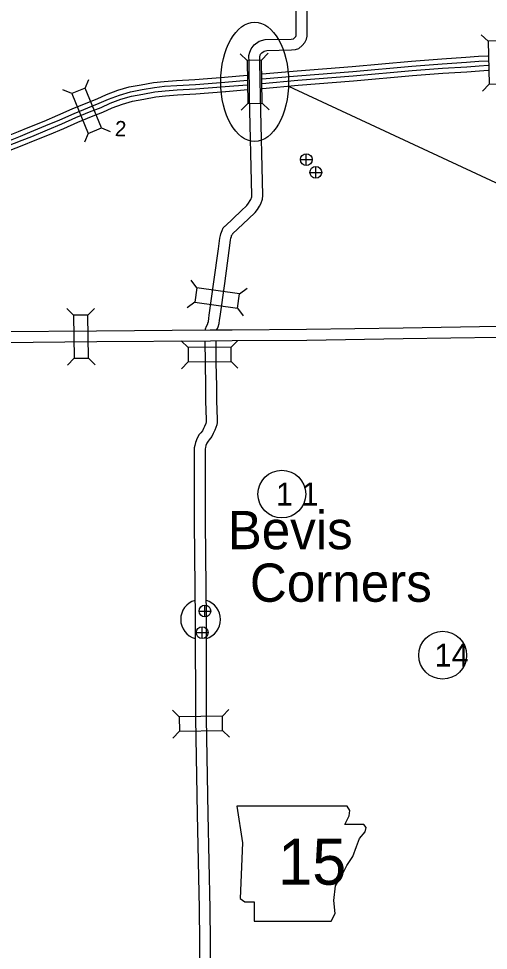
# Model space of a CAD drawing. Extents: x 1127717 to 1741049, y 2026793 to 2244711.
# Drawn here: x 1250609 to 1257093, y 2127719 to 2140586 of the extents above; entities that cross this region are included whole.
import ezdxf

# ---------------------------------------------------------------- set-up
doc = ezdxf.new("R2010")
doc.units = 0
for name, color, linetype in [('10', 7, 'Continuous'), ('15', 7, 'Continuous'), ('19', 7, 'Continuous'), ('20', 7, 'Continuous'), ('21', 7, 'Continuous'), ('24', 7, 'Continuous'), ('26', 7, 'Continuous'), ('27', 7, 'Continuous'), ('R_Draft', 7, 'Continuous')]:
    doc.layers.add(name, color=color, linetype=linetype)

msp = doc.modelspace()

# ---------------------------------------------------------------- linework, layer by layer
at = {"layer": '10'}
for points in [[(1253458, 2137722), (1253680, 2137932), (1253760, 2138007), (1253783, 2138037), (1253807, 2138073), (1253816, 2138090), (1253827, 2138123), (1253829, 2138145), (1253797, 2139504), (1253789, 2139984), (1253788, 2140075), (1253798, 2140122), (1253817, 2140171), (1253861, 2140222), (1253929, 2140273), (1254012, 2140297), (1254369, 2140303), (1254397, 2140305), (1254402, 2140307), (1254418, 2140320), (1254434, 2140340), (1254440, 2140351), (1254442, 2140361), (1254442, 2140382), (1254436, 2141102)], [(1253561, 2137613), (1253783, 2137823), (1253872, 2137907), (1253906, 2137951), (1253934, 2137994), (1253954, 2138028), (1253976, 2138095), (1253979, 2138142), (1253947, 2139506), (1253939, 2139986), (1253938, 2140060), (1253942, 2140080), (1253947, 2140093), (1253964, 2140112), (1253997, 2140137), (1254034, 2140148), (1254377, 2140153), (1254430, 2140158), (1254477, 2140175), (1254524, 2140213), (1254561, 2140258), (1254583, 2140301), (1254591, 2140344), (1254592, 2140381), (1254586, 2141104)], [(1253186, 2136293), (1253186, 2136300), (1253200, 2136338), (1253219, 2136373), (1253222, 2136381), (1253228, 2136403), (1253234, 2136443), (1253240, 2136493), (1253305, 2136951), (1253366, 2137405), (1253385, 2137552), (1253394, 2137593), (1253402, 2137616), (1253407, 2137636), (1253417, 2137661), (1253432, 2137695), (1253455, 2137719)], [(1253346, 2136292), (1253353, 2136306), (1253365, 2136331), (1253375, 2136374), (1253383, 2136422), (1253389, 2136474), (1253454, 2136930), (1253515, 2137386), (1253533, 2137526), (1253539, 2137553), (1253546, 2137576), (1253549, 2137589), (1253555, 2137600), (1253559, 2137610), (1253564, 2137616)], [(1253180, 2136131), (1253182, 2135831), (1253189, 2135508), (1253190, 2135304), (1253199, 2135052), (1253198, 2135020), (1253195, 2134997)], [(1253330, 2136133), (1253332, 2135833), (1253339, 2135510), (1253340, 2135307), (1253349, 2135053), (1253348, 2135009), (1253344, 2134977)], [(1253195, 2134997), (1253175, 2134953), (1253162, 2134925), (1253146, 2134894), (1253125, 2134865), (1253103, 2134843), (1253074, 2134794), (1253048, 2134734), (1253040, 2134692), (1253034, 2134660), (1253034, 2134554), (1253032, 2133629), (1253046, 2132288)], [(1253344, 2134977), (1253317, 2134901), (1253296, 2134858), (1253274, 2134815), (1253240, 2134767), (1253223, 2134750), (1253208, 2134725), (1253192, 2134690), (1253187, 2134663), (1253184, 2134645), (1253184, 2134555), (1253182, 2133629), (1253196, 2132288)], [(1253046, 2132288), (1253046, 2132281), (1253049, 2130919), (1253071, 2129599), (1253099, 2128295), (1253113, 2126929), (1253131, 2125874), (1253160, 2124567), (1253176, 2123596)], [(1253196, 2132288), (1253196, 2132282), (1253199, 2130920), (1253221, 2129602), (1253249, 2128294)], [(1253249, 2128294), (1253263, 2126931), (1253281, 2125876), (1253310, 2124570), (1253326, 2123596)]]:
    msp.add_lwpolyline(points, dxfattribs=at)
at = {"layer": '15'}
for points in [[(1253555, 2136290), (1254583, 2136297), (1255917, 2136317), (1257232, 2136339), (1258655, 2136352), (1259656, 2136361), (1259688, 2136363), (1259709, 2136364), (1259723, 2136366), (1259742, 2136370), (1259755, 2136376), (1259766, 2136383), (1259781, 2136395), (1259791, 2136405), (1259805, 2136422), (1259823, 2136442), (1259833, 2136461), (1259843, 2136485), (1259847, 2136495), (1259847, 2136494)], [(1253556, 2136140), (1254585, 2136147), (1255919, 2136167), (1257234, 2136189), (1258656, 2136202), (1259662, 2136211), (1259697, 2136213), (1259725, 2136214), (1259751, 2136219), (1259786, 2136226), (1259825, 2136242), (1259854, 2136261), (1259882, 2136284), (1259901, 2136304), (1259918, 2136323), (1259947, 2136355), (1259969, 2136397), (1259981, 2136426), (1259990, 2136446), (1259997, 2136478)], [(1247926, 2136233), (1248606, 2136243), (1250364, 2136263), (1251685, 2136275), (1253254, 2136287), (1253555, 2136290)], [(1247928, 2136083), (1248608, 2136093), (1250366, 2136113), (1251686, 2136125), (1253255, 2136137), (1253556, 2136140)]]:
    msp.add_lwpolyline(points, dxfattribs=at)
at = {"layer": '19'}
for points in [[(1253972, 2139823), (1254453, 2139865), (1255215, 2139925), (1256031, 2139998), (1256451, 2140031), (1256784, 2140052), (1256958, 2140066), (1257086, 2140073)], [(1253971, 2139691), (1254463, 2139734), (1255226, 2139794), (1256042, 2139868), (1256461, 2139900), (1256794, 2139921), (1256967, 2139935), (1257090, 2139942)], [(1253972, 2139754), (1254458, 2139797), (1255221, 2139857), (1256037, 2139930), (1256456, 2139962), (1256789, 2139984), (1256963, 2139997), (1257090, 2140004)], [(1253450, 2139778), (1253762, 2139805)], [(1253974, 2139623), (1254469, 2139666), (1255232, 2139726), (1256048, 2139799), (1256466, 2139831), (1256798, 2139853), (1256972, 2139866), (1257090, 2139873)], [(1249144, 2138753), (1249440, 2138784), (1249757, 2138813), (1249916, 2138830), (1249994, 2138845), (1250164, 2138876), (1250288, 2138907), (1250402, 2138946), (1250607, 2139028), (1250739, 2139082), (1250959, 2139171), (1251152, 2139252), (1251348, 2139340), (1251540, 2139418), (1251694, 2139480), (1251822, 2139539), (1251979, 2139597), (1252136, 2139642), (1252301, 2139672), (1252472, 2139704), (1252618, 2139720), (1252790, 2139733), (1253043, 2139747), (1253451, 2139778)], [(1249148, 2138685), (1249446, 2138715), (1249763, 2138745), (1249926, 2138762), (1250007, 2138778), (1250178, 2138809), (1250308, 2138841), (1250426, 2138882), (1250633, 2138964), (1250765, 2139018), (1250985, 2139108), (1251179, 2139189), (1251375, 2139276), (1251566, 2139355), (1251721, 2139417), (1251848, 2139475), (1252001, 2139531), (1252152, 2139575), (1252314, 2139605), (1252482, 2139636), (1252624, 2139652), (1252794, 2139664), (1253048, 2139678), (1253456, 2139709)], [(1253455, 2139709), (1253768, 2139736)], [(1253461, 2139647), (1253765, 2139674)], [(1249146, 2138553), (1249459, 2138585), (1249776, 2138614), (1249946, 2138632), (1250031, 2138649), (1250206, 2138680), (1250346, 2138716), (1250471, 2138759), (1250682, 2138842), (1250815, 2138897), (1251035, 2138987), (1251231, 2139069), (1251427, 2139156), (1251615, 2139233), (1251773, 2139296), (1251899, 2139354), (1252041, 2139407), (1252182, 2139447), (1252338, 2139476), (1252501, 2139506), (1252636, 2139521), (1252803, 2139533), (1253056, 2139547), (1253466, 2139579)], [(1249148, 2138622), (1249453, 2138653), (1249769, 2138683), (1249936, 2138700), (1250018, 2138716), (1250192, 2138747), (1250326, 2138781), (1250447, 2138823), (1250656, 2138906), (1250789, 2138960), (1251009, 2139050), (1251204, 2139132), (1251400, 2139219), (1251589, 2139297), (1251746, 2139359), (1251872, 2139418), (1252020, 2139472), (1252166, 2139514), (1252325, 2139543), (1252491, 2139574), (1252630, 2139589), (1252798, 2139602), (1253052, 2139616), (1253461, 2139647)], [(1253467, 2139579), (1253771, 2139605)]]:
    msp.add_lwpolyline(points, dxfattribs=at)
at = {"layer": '20'}
for p, q in [((1257088, 2140273), (1256992, 2140364)), ((1253763, 2140008), (1253668, 2140100)), ((1253961, 2140012), (1254053, 2140107)), ((1251525, 2139625), (1251576, 2139747)), ((1257104, 2139679), (1257013, 2139583)), ((1251342, 2139550), (1251220, 2139601)), ((1253773, 2139414), (1253682, 2139320)), ((1253971, 2139418), (1254066, 2139326)), ((1251751, 2139076), (1251872, 2139025)), ((1251567, 2139000), (1251516, 2138879)), ((1253069, 2136868), (1252990, 2136973)), ((1253657, 2136784), (1253763, 2136864)), ((1251368, 2136490), (1251274, 2136582)), ((1251566, 2136491), (1251658, 2136585)), ((1253041, 2136672), (1252936, 2136593)), ((1253629, 2136588), (1253709, 2136483)), ((1251566, 2136491), (1251368, 2136490)), ((1251368, 2136490), (1251373, 2135896)), ((1251571, 2135897), (1251566, 2136491)), ((1252947, 2136044), (1252852, 2136137)), ((1253541, 2136049), (1253633, 2136143)), ((1251373, 2135896), (1251281, 2135801)), ((1251373, 2135896), (1251571, 2135897)), ((1251571, 2135897), (1251665, 2135805)), ((1252948, 2135846), (1252856, 2135752)), ((1253542, 2135851), (1253636, 2135759)), ((1252827, 2130943), (1252732, 2131035)), ((1253421, 2130953), (1253512, 2131047)), ((1252830, 2130745), (1252738, 2130650)), ((1253424, 2130755), (1253519, 2130663))]:
    msp.add_line(p, q, dxfattribs=at)
for points in [[(1257302, 2139684), (1257286, 2140278), (1257088, 2140273), (1257104, 2139679)], [(1253763, 2140008), (1253773, 2139414), (1253971, 2139418), (1253961, 2140012)], [(1251342, 2139550), (1251567, 2139000), (1251751, 2139076), (1251525, 2139625)], [(1253657, 2136784), (1253069, 2136868), (1253041, 2136672), (1253629, 2136588)], [(1252948, 2135846), (1253542, 2135851), (1253541, 2136049), (1252947, 2136044)], [(1252830, 2130745), (1253424, 2130755), (1253421, 2130953), (1252827, 2130943)]]:
    msp.add_lwpolyline(points, close=True, dxfattribs=at)
at = {"layer": '21'}
msp.add_lwpolyline([(1253623, 2129710), (1253699, 2129203), (1253665, 2128433), (1253733, 2128391), (1253860, 2128391), (1253860, 2128120), (1254925, 2128120), (1254976, 2128230), (1254959, 2128408), (1254985, 2128611), (1255078, 2128771), (1255137, 2128890), (1255221, 2129017), (1255272, 2129152), (1255314, 2129262), (1255391, 2129355), (1255408, 2129414), (1255374, 2129456), (1255111, 2129456), (1255171, 2129575), (1255179, 2129651), (1255144, 2129710)], close=True, dxfattribs=at)
at = {"layer": '24'}
for start, end in [(106.3541, 254.011), (285.5447, 74.5258)]:
    msp.add_arc((1253121, 2132288), 275, start, end, dxfattribs=at)
at = {"layer": '26'}
for p, q in [((1254499, 2138639), (1254662, 2138639)), ((1254580, 2138558), (1254580, 2138720)), ((1254711, 2138382), (1254711, 2138545)), ((1254630, 2138463), (1254792, 2138463)), ((1253180, 2132324), (1253180, 2132486)), ((1253098, 2132405), (1253261, 2132405)), ((1253142, 2132026), (1253142, 2132188)), ((1253060, 2132107), (1253223, 2132107))]:
    msp.add_line(p, q, dxfattribs=at)
for centre in [(1254580, 2138639), (1254711, 2138463), (1253180, 2132405), (1253142, 2132107)]:
    msp.add_circle(centre, 81.2, dxfattribs=at)
at = {"layer": '27'}
for centre in [(1254242, 2134020), (1256462, 2131795)]:
    msp.add_circle(centre, 330, dxfattribs=at)
at = {"layer": 'R_Draft'}
msp.add_line((1254334, 2139654), (1270984, 2131900), dxfattribs=at)
msp.add_ellipse((1253867, 2139713), major_axis=(0, 824), ratio=0.567328, dxfattribs=at)

# ---------------------------------------------------------------- texts
at = {"layer": '20'}
msp.add_text('2', height=211, rotation=358, dxfattribs=at).set_placement((1251935, 2138964))
at = {"layer": '21'}
msp.add_text('15', height=633.6, dxfattribs=at).set_placement((1254190, 2128626))
at = {"layer": '24'}
for s, p in [('Bevis', (1253494, 2133259)), ('Corners', (1253801, 2132533))]:
    msp.add_text(s, height=528, dxfattribs=at).set_placement(p)
at = {"layer": '27'}
for s, p in [('1 1', (1254160, 2133862)), ('14', (1256350, 2131637))]:
    msp.add_text(s, height=316.8, dxfattribs=at).set_placement(p)

doc.saveas('drawing.dxf')
